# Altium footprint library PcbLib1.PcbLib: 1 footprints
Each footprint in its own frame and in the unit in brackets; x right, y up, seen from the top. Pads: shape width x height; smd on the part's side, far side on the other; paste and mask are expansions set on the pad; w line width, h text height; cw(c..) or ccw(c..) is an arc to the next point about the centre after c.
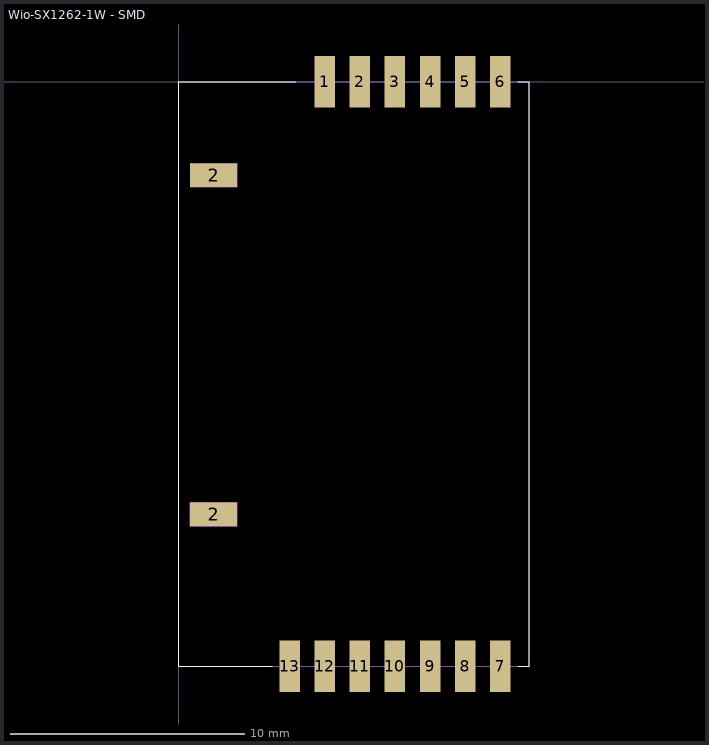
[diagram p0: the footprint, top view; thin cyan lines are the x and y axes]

## Wio-SX1262-1W - SMD [mm]
pads (15):
  rect 0.875x2.2 smd: 1(6.25,0) 2(7.75,0) 3(9.25,0) 4(10.75,0) 5(12.25,0) 6(13.75,0) 7(13.75,-25) 8(12.25,-25) 9(10.75,-25) 10(9.25,-25) 11(7.75,-25) 12(6.25,-25) 13(4.75,-25)
  rect 2x1 smd: 2(1.5,-18.5) 2(1.5,-4)
Top Overlay:
  lines w0.051: 4,-25 0,-25 0,0 5,0 ; 14.5,-25 15,-25 15,0 14.5,0
Mechanical 15:
  region: 2.5,-3.5 2.5,-4.512 0.5,-4.512 0.5,-3.5
  region: 2.5,-18 2.5,-19.012 0.5,-19.012 0.5,-18
  lines w0.025: 0,-7.135 0,0 3.265,0 ; 2.5,-18 2.5,-19 0.5,-19 0.5,-17.988 2.5,-17.988
  lines w0.051: 0,-25 0,0 15,0 15,-25 0,-25
3D body "Wio-SX1262-1W_V1.0.step": height 2.9, standoff 0.08, extent 0,-25 15,0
